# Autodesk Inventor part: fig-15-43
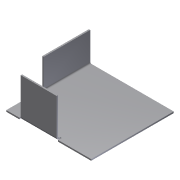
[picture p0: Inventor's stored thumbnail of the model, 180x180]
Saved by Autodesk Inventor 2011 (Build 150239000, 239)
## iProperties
Created: 2005-03
Part Number: fig-15-43
Document SubType Name: Sheet Metal
Designer: CADCIM
Manufacturer: Standard
Standards Organization: Custom
Density: 1 g/cm^3
Sheet Metal Rule: Default
Author: CADCIM
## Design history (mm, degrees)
node "Face1"
  sketch "Sketch1"
    geometry: L1 (-29, -26)-(30, -26); L2 (30, -26)-(30, 31.375); L3 (30, 31.375)-(-29, 31.375); L4 (-29, 31.375)-(-29, -26)
    constraints: 8 end point, 2 parallel, 1 horizontal, 1 perpendicular
node "Flange1"
node "Flange2"
body "Solid1"
face "Plate1" dims "Thickness" = 1
sketch "Sketch2"
  geometry: L1 (25, 0)-(57.375, 0); L2 (57.375, 0)-(57.375, 20); L3 (57.375, 20)-(25, 20); L4 (25, 20)-(25, 0)
  constraints: 8 end point
face "Plate2" dims "d1" = 0, "d2" = 25, "d3" = 1 (= BendReliefWidth), "d5" = 2 (= MinimumRemnant), "d7" = 20, "d8" = 90 deg, "d9" = 1 (= BendRadius), "Thickness" = 1
bend "Bend1" dims "d3" = 1 (= BendReliefWidth), "d4" = 0.5 (= BendReliefDepth), "d5" = 2 (= MinimumRemnant), "d6" = 1 (= BendRadius), "d7" = 20, "d8" = 90 deg, "d9" = 1 (= BendRadius), "SeamGap" = 0.01, "Thickness" = 1
sketch "Sketch3"
  geometry: L1 (49, 0)-(24, 0); L2 (24, 0)-(24, 26); L3 (24, 26)-(49, 26); L4 (49, 26)-(49, 0)
  constraints: 8 end point
face "Plate3" dims "d12" = 1 (= BendReliefWidth), "d14" = 2 (= MinimumRemnant), "d16" = 26, "d17" = 90 deg, "d18" = 1 (= BendRadius), "d19" = 10, "d20" = 25, "Thickness" = 1
bend "Bend2" dims "d12" = 1 (= BendReliefWidth), "d13" = 0.5 (= BendReliefDepth), "d14" = 2 (= MinimumRemnant), "d15" = 1 (= BendRadius), "d16" = 26, "d17" = 90 deg, "d18" = 1 (= BendRadius), "SeamGap" = 0.01, "Thickness" = 1
other parameters: "BendRadius" = 1 (= Thickness), "BendReliefWidth" = 1 (= Thickness), "BendReliefDepth" = 0.5 (= 0.5 x Thickness), "CornerReliefSize" = 4 (= 4 x Thickness), "MinimumRemnant" = 2 (= 2 x Thickness), "TransitionRadius" = 1 (= BendRadius), "d0" = 1 (= BendRadius), "JacobiRadiusSize" = 1 (= Thickness), "GapSize" = 1 (= Thickness)
